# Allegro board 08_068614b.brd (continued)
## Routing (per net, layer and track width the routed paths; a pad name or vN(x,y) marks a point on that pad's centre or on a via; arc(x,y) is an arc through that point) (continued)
V5_N: length 69.3
  L2_PWR w0.5: v2(94.05,31.26) 94.05,34.06 94.04,34.07
  L2_PWR w0.508: v2(119.35,43.48) v2(119.35,41.9) 119.35,39.47 113.13,33.25 v2(105.51,33.25) 104.69,34.07 101.48,34.07 ; 101.48,34.07 94.04,34.07 88.03,40.08 88.03,43.81 v2(87.46,44.38) 87.46,45.06 ; 101.48,34.07 v2(101.48,40.79) ; v2(89.77,45.06) 87.46,45.06 ; 87.46,45.06 v2(87.46,45.74)
  BOTTOM w0.2: U2.16 v2(101.48,40.79) ; U2.6 104.81,35.2 C52.1 ; R72.1 v2(119.35,41.9) ; R70.1 v2(119.35,43.48)
  BOTTOM w0.508: C52.1 v2(105.51,33.25) ; R68.1 v2(94.05,31.26) ; R61.2 v2(87.46,44.38) ; R82.1 v2(89.77,45.06) ; R78.1 v2(87.46,45.74)
V5_P: length 204.7
  L2_PWR w0.5: v2(89.64,126.94) 90.96,125.62
  L2_PWR w0.508: 105.38,121.2 105.38,125.62 ; 105.38,121.2 v2(105.38,121.19) ; 105.38,121.2 102.43,118.25 95.85,118.25 94.74,117.14 v2(94.74,116.13) ; 105.38,125.62 105.38,125.69 105.89,126.21 118.03,126.21 119.23,127.41 v2(119.23,129.84) v2(119.23,131.42) ; 105.38,125.62 90.96,125.62
  L3_SIG w0.6: 36.04,130.63 89.64,130.63 ; 89.64,130.63 v2(89.64,129.84) v2(89.64,126.94) ; 89.64,130.63 v2(89.64,131.42) v2(89.64,133)
  L3_SIG w0.635: v2(42.75,54.31) v2(42.75,55.01) v2(42.75,55.72) 32.4,66.08 32.4,126.99 36.04,130.63
  BOTTOM w0.2: U1.6 104.68,125.22
  BOTTOM w0.3: 104.68,125.22 104.68,123.15 C8.1
  BOTTOM w0.508: C8.1 v2(105.38,121.19) ; R25.1 v2(89.64,126.94) ; R22.1 v2(89.64,133) ; R15.1 v2(119.23,129.84) ; R13.1 v2(119.23,131.42) ; R7.2 v2(89.64,129.84) ; R11.1 v2(94.74,116.13) ; R24.1 v2(89.64,131.42)
VIN: length 50.2
  TOP w0.581: DS2.A v2(42.13,60.91)
  TOP w0.635: DS1.A v2(44.09,143.69)
  L4_SIG w0.508: v2(42.13,60.91) 35.79,67.24 v1(35.79,94.19)
  BOTTOM w0.581: 43.29,60.91 R65.1 43.29,62.39 44.02,63.12 R83.1 ; 43.29,60.91 R59.1 ; 43.29,60.91 v2(42.13,60.91)
  BOTTOM w0.635: R117.1 36.73,127.89 ; R117.1 36.02,128.46 ; R117.1 35.31,127.89 ; R28.1 46.85,143.69 v2(44.09,143.69)
  vias: v1(17.28,163.47) v1(17.28,160.93) v1(17.28,158.39) v1(17.28,155.85) v1(18.18,145.73) v1(18.18,120.33) v1(18.55,162.2) v1(18.55,159.66) v1(18.55,157.12) v1(19.82,163.47) v1(19.82,160.93) v1(19.82,158.39) v1(19.82,155.85) v1(19.81,149.59) v1(19.81,141.87) v1(19.81,124.19) v1(19.81,116.47) v1(21.09,157.11) v1(22.36,158.38) v1(22.36,155.84) v1(23.63,157.11) v1(23.67,151.22) v1(23.67,140.23) v1(23.67,125.82) v1(23.67,114.83) v1(24.9,158.38) v1(24.9,155.84) v1(26.17,157.11) v1(27.44,163.46) v1(27.44,160.92) v1(27.44,158.38) v1(27.44,155.84) v1(27.53,149.59) v1(27.53,141.87) v1(27.53,124.19) v1(27.53,116.47) v1(28.71,162.19) v1(28.71,159.65) v1(28.71,157.11) v1(29.16,145.73) v1(29.16,120.33) v1(29.98,163.46) v1(29.98,160.92) v1(29.98,158.38) v1(29.98,155.84) v1(35.78,106.89) v1(35.78,104.35) v1(35.78,101.81) v1(35.78,99.27) v1(35.79,96.73) v1(37.05,105.62) v1(37.05,103.08) v1(37.05,100.54) v1(37.05,98) v1(37.06,95.46) v1(38.32,106.89) v1(38.32,104.35) v1(38.32,101.81) v1(38.32,99.27) v1(38.33,96.73) v1(38.33,94.19) v1(39.59,105.62) v1(39.6,95.46) v1(40.86,106.89) v1(40.86,104.35) v1(40.87,96.73) v1(40.87,94.19) v1(42.13,105.62) v1(42.14,95.46) v1(43.4,106.89) v1(43.4,104.35) v1(43.41,96.73) v1(43.41,94.19)
DRVCC_N: length 22.5
  L3_SIG w0.5: v2(96.62,49.47) v2(97.39,49.47) 98.73,48.13 v2(103.43,48.13) v2(104.2,48.13) 110.38,48.13 v2(111.73,49.47) v2(112.5,49.47)
  BOTTOM w0.2: 104.44,49.42 104.44,49.8 ; 104.44,49.42 C51.2 103.19,49.42 103.81,48.8 U2.29 ; 104.44,49.42 104.44,49.04
DRVCC_P: length 20.9
  L3_SIG w0.625: v2(96.49,137.41) v2(97.26,137.41) 98.24,136.44 v2(103.31,136.44) v2(104.08,136.44) 110.63,136.44 v2(111.6,137.41) v2(112.37,137.41)
  BOTTOM w0.2: v2(97.26,137.41) v2(96.49,137.41) ; v2(104.08,136.44) v2(103.31,136.44) ; 103.68,136.74 U1.29
FAULT_N: length 80.2
  L3_SIG w0.2: v2(99.4,42.29) 97.79,42.29 94.96,45.12 92.85,45.12 v2(92.78,45.06) 92.43,45.06 91.4,44.03 91.4,41.39 90.44,40.43 54.61,40.43 48.4,46.64 48.4,64.82 v2(49.14,65.56)
  BOTTOM w0.2: U2.19 v2(99.4,42.29) ; Q15.1 v2(49.14,65.56) ; R82.2 v2(92.78,45.06)
PGATE: length 4.1
  BOTTOM w0.2: 105.68,134.74 U1.33
  BOTTOM w0.3: R27.2 107.79,136.32 107.28,135.81 106.49,135.81 105.68,135 105.68,134.74
RUN_N: length 18.4
  L3_SIG w0.2: v2(92.78,41.9) 92.78,40.38 94.37,38.8 99.25,38.8 100.49,40.04 100.49,41.36 100.92,41.79 v2(101.48,41.79)
  BOTTOM w0.2: R66.2 89.71,41.15 91.28,41.15 R67.1 v2(92.78,41.9) ; U2.18 v2(101.48,41.79)
RUN_P: length 145.3
  L3_SIG w0.2: v2(101.35,129.73) 101.92,129.16 101.92,127.98 99.93,125.99 P5.2 35.46,125.99 34.25,124.78 34.25,66.67 v2(45.01,55.91)
  BOTTOM w0.2: U1.18 v2(101.35,129.73)
UNNAMED_7_CAP_I29_N2: length 7.5
  BOTTOM w0.2: C5.2 98.17,122.46 99.72,122.46 102.18,124.93 U1.11
UNNAMED_7_CAP_I48_N1: length 1
  BOTTOM w0.2: R8.2 111.71,117.85 C4.1
UNNAMED_7_CAP_I49_N1: length 9
  BOTTOM w0.2: U1.3 106.18,125.13 109.14,122.17 111.04,122.17 111.29,121.92 111.29,121.57 C3.1 111.71,121.15 R8.1
UNNAMED_7_CAP_I67_N1: length 1
  BOTTOM w0.2: R5.2 109.31,117.85 C2.1
UNNAMED_7_CAP_I68_N1: length 7.1
  BOTTOM w0.2: U1.4 105.68,125.06 108.92,121.82 108.92,121.55 C1.1 109.31,121.15 R5.1
UNNAMED_7_CAP_I69_N2: length 1.6
  BOTTOM w0.2: U1.1 107.18,125.5 107.38,125.3 108.02,125.3 C6.2
UNNAMED_7_CAP_I83_N2: length 6.9
  BOTTOM w0.2: 104.68,134.74 U1.31
  BOTTOM w0.3: 104.68,134.74 104.68,135.01 105.83,136.16 C9.2 106.63,137.63 106.63,139.13 105.86,139.9 R31.1
UNNAMED_7_CAP_I87_N1: length 50.9
  TOP w0.2: Q5.2 v1(82.87,157.18) ; Q9.3 v1(90.09,157.18) ; Q5.3 v1(84.15,157.18) ; Q5.1 v1(81.59,157.18) ; Q9.1 v1(87.53,157.18) ; Q9.2 v1(88.81,157.18)
  L4_SIG w1: v2(95.11,123.96) 97.85,126.71 97.85,130.41 97.85,130.41 v2(97.85,131.36) 97.85,132.75 97.85,132.76 97.85,133.78 84.27,147.36 TP3.1
  BOTTOM w0.2: R45.1 94.42,125.44 95.11,124.75 v2(95.11,123.96) R43.1 ; 99.56,132.23 U1.23
  BOTTOM w0.3: 99.56,132.23 98.75,131.42 C11.1
  BOTTOM w0.5: C11.1 v2(97.85,131.36)
  vias: v1(79.44,149.97) v1(79.44,148.63) v1(79.44,147.3) v1(79.44,145.97) v1(80.77,149.97) v1(80.77,148.63) v1(80.77,147.3) v1(80.77,145.97) v1(90,155.91) v1(90,154.58) v1(90,153.25) v1(90,151.91) v1(90,149.97) v1(90,148.63) v1(90,147.3) v1(90,145.97) v1(91.33,155.91) v1(91.33,154.58) v1(91.33,153.25) v1(91.33,151.91) v1(91.33,149.97) v1(91.33,148.63) v1(91.33,147.3) v1(91.33,145.97) v1(92.67,155.91) v1(92.67,154.58) v1(92.67,153.25) v1(92.67,151.91) v1(92.67,149.97) v1(92.67,148.63) v1(92.67,147.3) v1(92.67,145.97)
UNNAMED_7_CAP_I93_N1: length 52.3
  TOP w0.2: Q7.2 v1(118.95,157.18) ; Q7.1 v1(117.67,157.18) ; Q7.3 v1(120.23,157.18) ; Q11.1 v1(123.61,157.18) ; Q11.2 v1(124.9,157.18) ; Q11.3 v1(126.18,157.18)
  L4_SIG w1: TP6.1 124.77,147.86 111.02,134.11 v2(111.02,131.36) 111.02,126.71 v2(113.76,123.96)
  BOTTOM w0.2: R46.1 v2(113.76,123.96) 113.76,124.76 114.44,125.44 R50.1 ; 120.38,148.64 120.38,147.3 ; 109.31,132.23 U1.38
  BOTTOM w0.3: C10.1 110.12,131.42 109.31,132.23
  BOTTOM w0.5: C10.1 v2(111.02,131.36)
  vias: v1(116.38,155.92) v1(116.38,154.58) v1(116.38,153.25) v1(116.38,151.92) v1(116.38,149.97) v1(116.38,148.64) v1(116.38,147.3) v1(116.38,145.97) v1(117.71,155.92) v1(117.71,154.58) v1(117.71,153.25) v1(117.71,151.92) v1(117.71,149.97) v1(117.71,148.64) v1(117.71,147.3) v1(117.71,145.97) v1(119.04,155.92) v1(119.04,154.58) v1(119.04,153.25) v1(119.04,151.92) v1(119.04,149.97) v1(119.04,148.64) v1(119.04,147.3) v1(119.04,145.97) v1(128.27,149.97) v1(128.27,148.63) v1(128.27,147.3) v1(128.27,145.97) v1(129.6,149.97) v1(129.6,148.63) v1(129.6,147.3) v1(129.6,145.97)
UNNAMED_7_CAP_I127_N1: length 7.3
  BOTTOM w0.2: 102.68,134.74 U1.27
  BOTTOM w0.3: R36.1 101.35,140.24 100.71,139.61 100.71,137.63 C12.1 101.51,136.19 102.68,135.02 102.68,134.74
UNNAMED_7_CAP_I149_N1: length 29.2
  TOP w0.2: R2.1 v2(127.71,123.18)
  L4_SIG w0.2: v2(127.71,123.18) 127.12,123.77 120.2,123.77 115.22,128.75 114.06,128.75 113.84,128.52 v2(113.84,127.73)
  BOTTOM w0.2: v2(113.84,127.73) 113.84,127.27 113.51,126.94 C26.1 113,125.41 R49.1 ; v2(113.84,127.73) 113.84,128.16 113.48,128.52 C29.1 ; v2(113.84,127.73) U1.47 ; R56.1 v2(127.71,123.18)
UNNAMED_7_CAP_I149_N2: length 6.2
  BOTTOM w0.2: U1.48 111.31,127.23 C26.2 111.6,125.41 R49.2 111.55,124.02 R46.2
UNNAMED_7_CAP_I199_N1: length 29
  TOP w0.2: R1.3 v2(81.33,123.18)
  L4_SIG w0.2: v2(81.33,123.18) 81.92,123.77 88.55,123.77 93.47,128.69 94.83,128.69 95.03,128.49 v2(95.03,127.73)
  BOTTOM w0.2: U1.14 v2(95.03,127.73) ; v2(95.03,127.73) 95.03,127.27 95.35,126.94 C25.1 95.86,125.41 R44.1 ; v2(95.03,127.73) 95.03,128.16 95.39,128.52 C27.1 ; R54.1 v2(81.33,123.18)
UNNAMED_7_CAP_I199_N2: length 8.9
  BOTTOM w0.2: 97.26,129.29 C27.2 97.55,128.23 U1.15 ; 97.26,129.29 94.65,129.29 93.8,128.44 R45.2 ; 97.26,129.29 97.26,130.05 R47.1
UNNAMED_7_CAP_I202_N2: length 6.2
  BOTTOM w0.2: U1.13 97.55,127.23 C25.2 97.26,125.41 R44.2 97.31,124.02 R43.2
UNNAMED_7_DIOLED_I185_N: length 2.3
  TOP w0.635: DS1.C v2(46.34,141.09)
  BOTTOM w0.635: R30.1 46.69,141.44 v2(46.34,141.09)
UNNAMED_7_ICLTC3871_I31_BOOST1: length 1.2
  BOTTOM w0.2: 108.55,133.6 U1.37
  BOTTOM w0.3: R119.1 108.55,133.6
UNNAMED_7_ICLTC3871_I31_BOOST2: length 1.2
  BOTTOM w0.2: 100.31,133.6 U1.24
  BOTTOM w0.3: R57.1 100.31,133.6
UNNAMED_7_ICLTC3871_I31_BUCK: length 14.9
  L3_SIG w0.2: v2(92.66,126.94) 99.56,126.94 v2(101.35,128.73)
  BOTTOM w0.2: v2(92.66,126.94) R25.2 91.15,126.2 89.6,126.2 88.87,126.93 R116.1 ; U1.16 v2(101.35,128.73)
UNNAMED_7_ICLTC3871_I31_DRVSET: length 15.1
  L3_SIG w0.2: v2(92.66,133) 94.87,130.78 101.3,130.78 v2(101.35,130.73)
  BOTTOM w0.2: U1.20 v2(101.35,130.73) ; R23.1 88.87,132.99 89.6,132.26 91.15,132.26 R22.2 v2(92.66,133)
UNNAMED_7_ICLTC3871_I31_FAULTN: length 63
  L3_SIG w0.2: v2(50.3,149.94) 50.3,145.72 61.67,134.35 89.73,134.35 v2(92.66,131.42) 94.55,129.53 98,129.53 98.71,130.23 v2(99.28,130.23)
  BOTTOM w0.2: U1.19 v2(99.28,130.23) ; R24.2 v2(92.66,131.42)
  BOTTOM w0.508: Q1.1 v2(50.3,149.94)
UNNAMED_7_ICLTC3871_I31_FREQ: length 12.1
  L3_SIG w0.2: v2(107.51,129.73) 108.57,130.78 114.35,130.78 116.21,132.64 v2(116.21,133)
  BOTTOM w0.2: U1.43 v2(107.51,129.73) ; R19.2 v2(116.21,133)
UNNAMED_7_ICLTC3871_I31_ILIM: length 12.8
  L3_SIG w0.2: v2(92.66,129.84) 93.83,128.66 98.71,128.66 v2(99.28,129.23)
  BOTTOM w0.2: U1.17 v2(99.28,129.23) ; R9.2 88.87,129.83 89.6,129.09 91.15,129.09 R7.1 v2(92.66,129.84)
UNNAMED_7_ICLTC3871_I31_MODE: length 12.9
  L3_SIG w0.2: v2(116.21,129.84) 114.95,128.59 110.23,128.59 v2(109.59,129.23)
  BOTTOM w0.2: U1.44 v2(109.59,129.23) ; R16.1 119.3,129.09 117.71,129.09 R15.2 v2(116.21,129.84)
UNNAMED_7_ICLTC3871_I31_OVHIGH: length 8.6
  BOTTOM w0.2: U1.8 103.68,124.7 101.85,122.87 R21.1 101.06,120.66 R20.1
UNNAMED_7_ICLTC3871_I31_OVLOW: length 9.8
  BOTTOM w0.2: R6.2 97.9,120.66 R10.1 99.3,122.06 99.88,122.06 102.68,124.86 U1.10
UNNAMED_7_ICLTC3871_I31_PHSMD: length 15.9
  L3_SIG w0.2: v2(116.21,131.42) 114.19,129.4 110.93,129.4 110.16,130.18 109.27,130.18 107.83,128.73 v2(107.51,128.73)
  BOTTOM w0.2: v2(116.21,131.42) R13.2 117.71,130.68 119.3,130.68 R14.2 ; U1.45 v2(107.51,128.73)
UNNAMED_7_ICLTC3871_I31_SETCUR: length 11.9
  BOTTOM w0.2: U1.12 101.68,125 99.55,122.86 96.94,122.86 R12.2 94.74,120.66 R11.2
UNNAMED_7_ICLTC3871_I31_SNSD1: length 8.9
  BOTTOM w0.2: 111.6,129.29 C29.2 111.31,128.23 U1.46 ; 111.6,129.29 114.22,129.29 115.06,128.44 R50.2 ; 111.6,129.29 R52.1
UNNAMED_7_ICLTC3871_I31_TG1: length 9.6
  L2_PWR w0.508: v2(114.45,132.16) 112.62,132.16 111.95,132.83 108.61,132.83 v2(107.51,131.73)
  BOTTOM w0.2: U1.39 v2(107.51,131.73)
  BOTTOM w0.5: v2(114.45,132.16) R32.1
UNNAMED_7_ICLTC3871_I31_TG2: length 9.7
  L2_PWR w0.508: v2(94.43,132.16) 96.27,132.16 97.09,132.98 100.1,132.98 v2(101.35,131.73)
  BOTTOM w0.2: U1.22 v2(101.35,131.73)
  BOTTOM w0.5: v2(94.43,132.16) R34.1
UNNAMED_7_ICLTC3871_I31_UVHIGH: length 9
  BOTTOM w0.2: R17.1 99.48,120.66 R18.1 100.27,121.89 103.18,124.8 U1.9
UNNAMED_7_IND_I144_N2: length 1.9
  BOTTOM w0.2: R53.2 v2(131.84,124.76)
  vias: v1(128.27,139.82) v1(128.27,138.48) v1(128.27,137.15) v1(128.27,135.82) v1(129.6,139.82) v1(129.6,138.48) v1(129.6,137.15) v1(129.6,135.82) v1(130.51,128.9) v1(131.84,128.9) v1(133.18,128.9)
UNNAMED_7_IND_I265_N1: length 1.9
  BOTTOM w0.2: R48.2 v2(77.21,124.76)
  vias: v1(75.88,128.9) v1(77.21,128.9) v1(78.55,128.9) v1(79.44,139.82) v1(79.44,138.48) v1(79.44,137.15) v1(79.44,135.82) v1(80.77,139.82) v1(80.77,138.48) v1(80.77,137.15) v1(80.77,135.82)
UNNAMED_7_NCTESTPAD_I102_N1: length 23.9
  TOP w0.65: Q12.4 v1(114.32,145.01) ; Q8.4 v1(114.32,150.95)
  L4_SIG w1: v2(111,138.58) 111,138.61 114.32,141.94 v1(114.32,145.01) v1(114.32,150.95) 114.36,150.99 TP8.1
  BOTTOM w0.508: R33.2 v2(111,138.58)
UNNAMED_7_NCTESTPAD_I215_N1: length 45.7
  TOP w0.65: Q5.4 v1(86.47,158.48) ; Q9.4 v1(92.41,158.48)
  L3_SIG w1: TP4.1 79.57,158.48 v1(86.47,158.48) v1(92.41,158.48)
  L4_SIG w1: v2(93.32,134.61) 82.32,145.61 82.32,153.03 79.53,155.82 TP4.1
  BOTTOM w0.5: R34.2 94.31,134.61 v2(93.32,134.61)
UNNAMED_7_NCTESTPAD_I219_N1: length 24.8
  TOP w0.65: Q6.4 v1(94.72,150.93) ; Q10.4 94.72,157.85 TP5.1
  L4_SIG w1: v2(97.86,138.58) 97.86,138.59 94.72,141.74 v1(94.72,150.93) 94.68,150.96 TP5.1
  BOTTOM w0.508: R35.2 v2(97.86,138.58)
UNNAMED_7_RES_I45_N2: length 40.9
  TOP w0.65: TP7.1 129.46,158.48 Q11.4 ; Q7.4 v1(122.55,158.48)
  L3_SIG w1: v1(122.55,158.48) 129.46,158.48 TP7.1
  L4_SIG w1: TP7.1 129.51,156.84 126.67,154 126.67,145.73 v2(115.55,134.61)
  BOTTOM w0.5: R32.2 114.57,134.61 v2(115.55,134.61)
UNNAMED_7_RES_I133_N1: length 1.1
  BOTTOM w0.2: R37.2 107.01,117.95 R38.1
UNNAMED_7_RES_I157_N1: length 0.8
  BOTTOM w0.2: R41.1 R40.1
UNNAMED_7_RES_I157_N2: length 10.8
  BOTTOM w0.2: R42.1 113.91,120.45 R41.2 113.69,121.47 113.69,121.82 112.95,122.57 109.3,122.57 106.68,125.19 U1.2
UNNAMED_7_RES_I183_N2: length 2.4
  BOTTOM w0.635: R30.2 49.31,141.74 Q4.3
UNNAMED_7_RES_I188_N1: length 68
  L4_SIG w0.635: v2(107.4,139.46) 107.4,163.11 112.15,167.86 v1(138.44,167.86) v1(138.44,175.22)
  BOTTOM w0.2: v2(107.4,139.46) 107.4,138.78 107.6,138.58 R27.1
  BOTTOM w0.508: Q2.1 v1(138.44,167.86) ; Q3.1 v1(138.44,175.22)
UNNAMED_7_RES_I194_N1: length 20.1
  TOP w0.2: R2.3 v2(127.71,124.76)
  L4_SIG w0.2: v2(113.86,130.05) 113.86,129.35 114.06,129.15 115.43,129.15 120.41,124.17 127.11,124.17 v2(127.71,124.76)
  BOTTOM w0.2: R53.1 v2(127.71,124.76) ; R52.2 v2(113.86,130.05)
UNNAMED_7_RES_I205_N2: length 20.1
  TOP w0.2: R1.1 v2(81.33,124.76)
  L4_SIG w0.2: v2(81.33,124.76) 81.93,124.17 88.38,124.17 93.3,129.09 94.83,129.09 95.05,129.31 v2(95.05,130.1)
  BOTTOM w0.2: R47.2 v2(95.05,130.1) ; R48.1 v2(81.33,124.76)
UNNAMED_7_TRAN2N7002_I177_D: length 4.7
  BOTTOM w0.635: R28.2 49.31,144.04 Q4.1 50.49,144.25 R29.1 50.49,146.22 Q1.3
UNNAMED_9_CAP_I9_N1: length 7.1
  BOTTOM w0.2: U2.4 105.81,37.12 109.05,33.88 109.05,33.61 C45.1 109.44,33.21 R58.1
UNNAMED_9_CAP_I11_N1: length 1
  BOTTOM w0.2: R58.2 109.44,29.91 C46.1
UNNAMED_9_CAP_I13_N1: length 9
  BOTTOM w0.2: U2.3 106.31,37.18 109.29,34.2 111.2,34.2 111.42,33.97 111.42,33.63 C47.1 111.84,33.21 R62.1
UNNAMED_9_CAP_I15_N1: length 1
  BOTTOM w0.2: R62.2 111.84,29.91 C48.1
UNNAMED_9_CAP_I43_N2: length 7.5
  BOTTOM w0.2: U2.11 102.31,36.99 99.84,34.52 98.3,34.52 C49.2
UNNAMED_9_CAP_I53_N2: length 1.6
  BOTTOM w0.2: U2.1 107.31,37.56 107.51,37.36 108.15,37.36 C50.2
UNNAMED_9_CAP_I61_N2: length 7.3
  BOTTOM w0.2: 104.81,46.8 U2.31
  BOTTOM w0.3: 104.81,46.8 104.81,47.18 105.86,48.23 105.86,48.58 C53.2 106.42,48.89 106.96,49.43 106.96,51.47 106.47,51.95 R86.1
UNNAMED_9_CAP_I91_N1: length 59.4
  TOP w0.2: Q21.3 v1(84.65,76.93) ; Q17.3 v1(90.6,76.93) ; Q17.2 v1(89.32,76.93) ; Q21.2 v1(83.37,76.93) ; Q21.1 v1(82.09,76.93) ; Q17.1 v1(88.04,76.93)
  L4_SIG w1: v2(95.23,36.02) 95.23,36.92 97.98,39.66 v2(97.98,43.42) 97.98,43.86 99.1,44.98 99.1,49.69 96.58,52.21 96.58,57.34 84.78,69.14 TP11.1
  BOTTOM w0.2: R98.1 v2(95.23,36.02) 95.23,36.81 94.55,37.5 R100.1 ; 99.68,44.29 U2.23
  BOTTOM w0.3: 99.68,44.29 98.88,43.48 C55.1
  BOTTOM w0.5: C55.1 v2(97.98,43.42)
  vias: v1(79.95,69.72) v1(79.95,68.39) v1(79.95,67.05) v1(79.95,65.72) v1(81.28,69.72) v1(81.28,68.39) v1(81.28,67.05) v1(81.28,65.72) v1(90.51,75.67) v1(90.51,74.33) v1(90.51,73) v1(90.51,71.66) v1(90.51,69.72) v1(90.51,68.38) v1(90.51,67.05) v1(90.51,65.72) v1(91.84,75.67) v1(91.84,74.33) v1(91.84,73) v1(91.84,71.66) v1(91.84,69.72) v1(91.84,68.38) v1(91.84,67.05) v1(91.84,65.72) v1(93.17,75.67) v1(93.17,74.33) v1(93.17,73) v1(93.17,71.66) v1(93.17,69.72) v1(93.17,68.38) v1(93.17,67.05) v1(93.17,65.72)
UNNAMED_9_CAP_I93_N1: length 59.4
  TOP w0.2: Q23.3 v1(125.82,76.93) ; Q19.2 v1(118.59,76.93) ; Q19.3 v1(119.87,76.93) ; Q23.1 v1(123.26,76.93) ; Q19.1 v1(117.31,76.93) ; Q23.2 v1(124.54,76.93)
  L4_SIG w1: v2(113.89,36.02) 113.89,36.92 111.14,39.66 v2(111.14,43.42) 111.14,43.84 110.02,44.96 110.02,49.67 112.54,52.19 112.54,57.29 124.41,69.17 TP14.1
  BOTTOM w0.2: R101.1 v2(113.89,36.02) 113.89,36.82 114.56,37.5 R105.1 ; 109.43,44.29 U2.38
  BOTTOM w0.3: C54.1 110.24,43.48 109.43,44.29
  BOTTOM w0.5: C54.1 v2(111.14,43.42)
  vias: v1(116.02,75.67) v1(116.02,74.34) v1(116.02,73) v1(116.02,71.67) v1(116.02,69.72) v1(116.02,68.39) v1(116.02,67.05) v1(116.02,65.72) v1(117.35,75.67) v1(117.35,74.34) v1(117.35,73) v1(117.35,71.67) v1(117.35,69.72) v1(117.35,68.39) v1(117.35,67.05) v1(117.35,65.72) v1(118.69,75.67) v1(118.69,74.34) v1(118.69,73) v1(118.69,71.67) v1(118.69,69.72) v1(118.69,68.39) v1(118.69,67.05) v1(118.69,65.72) v1(127.92,69.72) v1(127.92,68.39) v1(127.92,67.05) v1(127.92,65.72) v1(129.25,69.72) v1(129.25,68.39) v1(129.25,67.05) v1(129.25,65.72)
UNNAMED_9_CAP_I95_N1: length 7.7
  BOTTOM w0.2: 102.81,46.8 U2.27
  BOTTOM w0.3: R91.1 101.17,52.3 100.75,51.88 100.75,49.55 101.41,48.89 C56.1 101.94,48.61 101.94,48.05 102.81,47.18 102.81,46.8
UNNAMED_9_CAP_I126_N1: length 28.7
  TOP w0.2: R3.1 v2(94.51,53.37)
  L5_GND w0.2: v2(95.15,39.79) 95.15,40.55 95.38,40.77 96.38,40.77 97.12,41.52 97.12,47.59 93.93,50.78 93.93,52.78 v2(94.51,53.37)
  BOTTOM w0.2: C74.1 95.51,40.58 95.15,40.22 v2(95.15,39.79) ; v2(95.15,39.79) U2.14 ; v2(95.15,39.79) 95.15,39.32 95.48,39 C69.1 95.99,37.47 R99.1 ; R109.1 94.51,53.37 v2(94.51,53.37)
UNNAMED_9_CAP_I126_N2: length 6.2
  BOTTOM w0.2: R98.2 97.44,36.08 R99.2 97.39,37.47 C69.2 97.68,39.29 U2.13
UNNAMED_9_CAP_I130_N2: length 8.9
  BOTTOM w0.2: U2.15 97.68,40.29 C74.2 97.39,41.34 ; 97.39,41.34 94.78,41.34 93.93,40.5 R100.2 ; 97.39,41.34 97.39,42.11 R102.1
UNNAMED_9_CAP_I138_N1: length 28.7
  TOP w0.2: R4.3 v2(114.66,53.37)
  L5_GND w0.2: v2(114.66,53.37) 115.24,52.78 115.24,50.76 112.02,47.54 112.02,41.54 112.79,40.77 113.77,40.77 113.97,40.57 v2(113.97,39.79)
  BOTTOM w0.2: R111.1 114.66,53.37 v2(114.66,53.37) ; U2.47 v2(113.97,39.79) ; v2(113.97,39.79) 113.97,40.22 113.6,40.58 C77.1 ; v2(113.97,39.79) 113.97,39.32 113.64,39 C71.1 113.13,37.47 R104.1
UNNAMED_9_CAP_I138_N2: length 6.2
  BOTTOM w0.2: U2.48 111.44,39.29 C71.2 111.73,37.47 R104.2 111.68,36.08 R101.2
UNNAMED_9_CAP_I143_N2: length 8.9
  BOTTOM w0.2: 111.73,41.34 C77.2 111.44,40.29 U2.46 ; 111.73,41.34 R107.1 ; 111.73,41.34 114.34,41.34 115.19,40.5 R105.2
UNNAMED_9_DIOLED_I242_N: length 10.9
  TOP w0.581: DS2.C v2(42.13,64.38)
  L4_SIG w0.635: v2(46.49,71.68) 46.49,68.75 v2(42.13,64.38)
  BOTTOM w0.2: v2(46.49,71.68) 46.49,71.3 46.49,71.3 R85.1
UNNAMED_9_ICLTC3871_I21_BOOST1: length 1.2
  BOTTOM w0.2: 108.68,45.65 U2.37
  BOTTOM w0.3: R123.1 108.68,45.65
UNNAMED_9_ICLTC3871_I21_BOOST2: length 1.2
  BOTTOM w0.2: 100.44,45.65 U2.24
  BOTTOM w0.3: R122.1 100.44,45.65
UNNAMED_9_ICLTC3871_I21_DRVSET: length 16.3
  L3_SIG w0.2: v2(92.78,46.64) 94.85,46.64 95.49,47.28 96.99,47.28 v2(101.48,42.79)
  BOTTOM w0.2: v2(92.78,46.64) R79.1 91.28,45.9 89.71,45.9 R78.2 ; U2.20 v2(101.48,42.79)
UNNAMED_9_ICLTC3871_I21_FREQ: length 12.4
  L3_SIG w0.2: v2(116.34,45.06) 116.34,44.76 114.43,42.85 108.13,42.85 107.64,42.36 v2(107.64,41.79)
  BOTTOM w0.2: U2.43 v2(107.64,41.79) ; R77.1 v2(116.34,45.06)
UNNAMED_9_ICLTC3871_I21_ILIM: length 13.5
  L3_SIG w0.2: v2(92.78,43.48) 93.35,43.48 93.94,42.89 93.94,42.02 94.68,41.29 v2(99.4,41.29)
  BOTTOM w0.2: v2(92.78,43.48) R63.2 91.28,42.73 89.71,42.73 R61.1 ; U2.17 v2(99.4,41.29)
UNNAMED_9_ICLTC3871_I21_MODE: length 13.1
  L3_SIG w0.2: v2(109.72,41.29) 110.59,40.41 114.85,40.41 v2(116.34,41.9)
  BOTTOM w0.2: U2.44 v2(109.72,41.29) ; v2(116.34,41.9) R72.2 117.84,41.15 119.43,41.15 R74.1
UNNAMED_9_ICLTC3871_I21_OVHIGH: length 8.6
  BOTTOM w0.2: U2.8 103.81,36.75 101.98,34.92 R81.1 101.19,32.72 R80.1
UNNAMED_9_ICLTC3871_I21_OVLOW: length 9.8
  BOTTOM w0.2: U2.10 102.81,36.92 100.01,34.12 99.43,34.12 R69.1 98.03,32.72 R64.2
UNNAMED_9_ICLTC3871_I21_PHSMD: length 16.3
  L3_SIG w0.2: v2(116.34,43.48) 116.34,43.16 114.43,41.25 111.12,41.25 110.13,42.24 109.45,42.24 107.99,40.79 v2(107.64,40.79)
  BOTTOM w0.2: U2.45 v2(107.64,40.79) ; v2(116.34,43.48) R70.2 117.84,42.73 119.43,42.73 R71.2
UNNAMED_9_ICLTC3871_I21_SETCUR: length 10.1
  BOTTOM w0.2: U2.12 101.81,37.05 99.68,34.92 97.06,34.92 95.65,33.51 R73.1 94.06,33.51 R68.2
UNNAMED_9_ICLTC3871_I21_TG1: length 9.6
  L2_PWR w0.508: v2(114.58,44.21) 112.64,44.21 111.9,44.95 108.8,44.95 v2(107.64,43.79)
  BOTTOM w0.2: U2.39 v2(107.64,43.79)
  BOTTOM w0.508: R87.1 v2(114.58,44.21)
UNNAMED_9_ICLTC3871_I21_TG2: length 9.7
  L2_PWR w0.508: v2(94.54,44.21) 96.31,44.21 97.12,45.03 100.24,45.03 v2(101.48,43.79)
  BOTTOM w0.2: U2.22 v2(101.48,43.79)
  BOTTOM w0.508: R89.1 v2(94.54,44.21)
UNNAMED_9_ICLTC3871_I21_UVHIGH: length 9
  BOTTOM w0.2: R75.1 99.61,32.72 R76.1 100.4,33.94 103.31,36.86 U2.9
UNNAMED_9_ICLTC3871_I21_VFBLOW: length 10.8
  BOTTOM w0.2: U2.2 106.81,37.25 109.46,34.6 113.1,34.6 113.82,33.88 113.82,33.53 R96.2 114.04,32.51 R97.1
UNNAMED_9_IND_I114_N1: length 1.9
  BOTTOM w0.2: v2(92.93,57.5) 92.93,55.62 R103.2
  vias: v1(79.95,59.57) v1(79.95,58.24) v1(79.95,56.9) v1(79.95,55.57) v1(81.28,59.57) v1(81.28,58.24) v1(81.28,56.9) v1(81.28,55.57) v1(89.2,58.84) v1(89.2,57.51) v1(89.2,56.17)
UNNAMED_9_IND_I133_N2: length 1.9
  BOTTOM w0.2: v2(116.24,57.5) 116.23,57.49 R108.2
  vias: v1(119.96,58.81) v1(119.96,57.48) v1(119.96,56.15) v1(127.92,59.57) v1(127.92,58.24) v1(127.92,56.9) v1(127.92,55.57) v1(129.25,59.57) v1(129.25,58.24) v1(129.25,56.9) v1(129.25,55.57)
UNNAMED_9_NCTESTPAD_I80_N1: length 31.7
  TOP w0.508: Q22.4 v1(95.23,70.68)
  TOP w0.66: TP13.1 95.23,77.6 Q18.4
  L4_SIG w1: TP13.1 95.23,77.6 v1(95.23,70.68) 95.23,64.8 99.1,60.93 v2(99.1,52.49)
  BOTTOM w0.5: R90.2 99.09,52.48 v2(99.1,52.49)
UNNAMED_9_NCTESTPAD_I83_N1: length 52.5
  TOP w0.508: Q17.4 v1(92.92,78.24) ; Q21.4 v1(86.97,78.24)
  L3_SIG w1: TP12.1 80.08,78.24 v1(86.97,78.24) v1(92.92,78.24)
  L4_SIG w1: v2(94.54,47.81) 82.92,59.43 82.92,73.7 80.04,76.57 TP12.1
  BOTTOM w0.508: R89.2 v2(94.54,47.81)
UNNAMED_9_NCTESTPAD_I104_N1: length 30.7
  TOP w0.508: Q24.4 v1(113.97,70.71) ; Q20.4 v1(113.97,64.76)
  L4_SIG w1: TP16.1 113.97,77.6 v1(113.97,70.71) v1(113.97,64.76) 110.02,60.81 v2(110.02,52.51)
  BOTTOM w0.5: v2(110.02,52.51) 110.03,52.5 R88.2
UNNAMED_9_NCTESTPAD_I109_N1: length 47.6
  TOP w0.508: Q19.4 v1(122.19,78.24)
  TOP w0.65: Q23.4 129.11,78.24 TP15.1
  L3_SIG w1: v1(122.19,78.24) 129.11,78.24 TP15.1
  L4_SIG w1: TP15.1 129.15,76.52 126.3,73.67 126.3,59.54 v2(114.58,47.81)
  BOTTOM w0.508: R87.2 v2(114.58,47.81)
UNNAMED_9_RES_I102_N1: length 0.8
  BOTTOM w0.2: R96.1 R95.1
UNNAMED_9_RES_I115_N1: length 19
  TOP w0.2: R3.3 v2(92.93,53.37)
  L5_GND w0.2: v2(92.93,53.37) 93.53,52.77 93.53,50.62 96.72,47.42 96.72,41.69 96.21,41.18 95.38,41.18 95.18,41.38 v2(95.18,42.16)
  BOTTOM w0.2: R102.2 v2(95.18,42.16) ; R103.1 92.94,53.37 v2(92.93,53.37)
UNNAMED_9_RES_I134_N1: length 19
  TOP w0.2: R4.1 v2(116.24,53.37)
  L5_GND w0.2: v2(116.24,53.37) 115.64,52.77 115.64,50.59 112.42,47.37 112.42,41.71 112.95,41.18 113.79,41.18 113.99,41.38 v2(113.99,42.11)
  BOTTOM w0.2: R108.1 116.24,54.11 v2(116.24,53.37) ; R107.2 v2(113.99,42.11)
UNNAMED_9_RES_I145_N1: length 1.1
  BOTTOM w0.2: R92.2 107.14,30.01 R93.1
UNNAMED_9_RES_I232_N1: length 2.9
  BOTTOM w0.2: R59.2 46.09,59.93 Q14.1 46.09,58.73 R60.1
UNNAMED_9_RES_I232_N2: length 2.9
  BOTTOM w0.2: Q13.3 48.19,55.95 47.31,56.83 R60.2
UNNAMED_9_RES_I235_N1: length 54
  L3_SIG w0.2: v2(49.37,60.89) 49.37,48.9 56.37,41.9 v2(86.7,41.9)
  BOTTOM w0.2: R66.1 v2(86.7,41.9) ; Q14.3 v2(49.37,60.89)
UNNAMED_9_RES_I236_N2: length 1.3
  BOTTOM w0.2: R65.2 Q14.2
UNNAMED_9_RES_I239_N1: length 6.1
  BOTTOM w0.2: Q15.3 44.81,64.62 R83.2 44.59,64.84 R84.1 45.88,67.6 Q16.1
UNNAMED_9_RES_I244_N2: length 2.7
  BOTTOM w0.2: Q16.3 48.19,68.35 47.99,68.55 R85.2
UNNAMED_9_RES_I291_N2: length 2.4
  BOTTOM w0.2: Q13.1 45.07,55.01 R120.2 44.97,54.08 R121.1
VFBHIGH_N: length 6.4
  BOTTOM w0.2: U2.5 105.31,36.98 106.94,35.35 R94.1 107.14,33.11 R93.2
VFBHIGH_P: length 6.4
  BOTTOM w0.2: R38.2 107.01,121.05 R39.1 106.81,123.29 105.18,124.92 U1.5
VHIGH: length 99.6
  TOP w0.6: J1.1 161.55,165.15 161.14,165.56 C115.2
  L4_SIG w0.508: v2(99.48,116.13) v2(101.06,116.13) 114.3,116.13 115.44,117.27 115.44,119.94 117.31,121.81 134.23,121.81 158.15,145.73 158.15,159.5 159.87,161.22 v1(159.87,166.78)
  BOTTOM w0.2: R17.2 v2(99.48,116.13) ; R20.2 v2(101.06,116.13)
  vias: v1(17.28,173.63) v1(17.28,171.09) v1(17.28,168.55) v1(17.28,166.01) v1(18.55,172.36) v1(18.55,169.82) v1(18.55,167.28) v1(19.82,173.63) v1(19.82,171.09) v1(19.82,168.55) v1(19.82,166.01) v1(21.09,172.37) v1(22.36,173.64) v1(22.36,171.1) v1(23.63,172.37) v1(24.9,173.64) v1(24.9,171.1) v1(26.17,172.37) v1(27.44,173.64) v1(27.44,171.1) v1(27.44,168.56) v1(27.44,166.02) v1(28.71,172.37) v1(28.71,169.83) v1(28.71,167.29) v1(29.98,173.64) v1(29.98,171.1) v1(29.98,168.56) v1(29.98,166.02) v1(98.16,191.19) v1(98.16,188.65) v1(98.16,186.11) v1(99.43,189.92) v1(99.43,187.38) v1(100.7,191.19) v1(100.7,188.65) v1(100.7,186.11) v1(101.97,189.93) v1(103.24,191.2) v1(103.24,188.66) v1(104.51,189.93) v1(105.78,191.2) v1(105.78,188.66) v1(107.05,189.93) v1(108.32,191.2) v1(108.32,188.66) v1(108.32,186.12) v1(109.59,189.93) v1(109.59,187.39) v1(110.86,191.2) v1(110.86,188.66) v1(110.86,186.12) v1(142.88,178.11) v1(142.88,176.77) v1(142.88,175.44) v1(142.88,174.11) v1(142.88,170.74) v1(142.88,169.41) v1(142.88,168.07) v1(142.88,166.74) v1(144.22,178.11) v1(144.22,176.77) v1(144.22,175.44) v1(144.22,174.11) v1(144.22,170.74) v1(144.22,169.41) v1(144.22,168.07) v1(144.22,166.74) v1(145.55,178.11) v1(145.55,176.77) v1(145.55,175.44) v1(145.55,174.11) v1(145.55,170.74) v1(145.55,169.41) v1(145.55,168.07) v1(145.55,166.74) v1(146.88,178.11) v1(146.88,176.77) v1(146.88,175.44) v1(146.88,174.11) v1(146.88,170.74) v1(146.88,169.41) v1(146.88,168.07) v1(146.88,166.74) v1(155.02,188.79) v1(155.02,186.25) v1(155.02,183.71) v1(155.02,181.17) v1(155.03,178.63) v1(155.03,176.09) v1(156.29,187.52) v1(156.29,184.98) v1(156.29,182.44) v1(156.29,179.9) v1(156.3,177.36) v1(157.56,188.79) v1(157.56,186.25) v1(157.56,183.71) v1(157.56,181.17) v1(157.57,178.63) v1(157.57,176.09) v1(158.83,187.52) v1(158.84,177.36) v1(160.1,188.79) v1(160.1,186.25) v1(160.11,178.63) v1(160.11,176.09) v1(161.37,187.52) v1(161.38,177.36) v1(162.64,188.79) v1(162.64,186.25) v1(162.65,178.63) v1(162.65,176.09)
VHIGH_P: length 129.6
  L4_SIG w0.5: v2(108.31,118.65) 107.06,117.4 75.18,117.4 74.14,118.44 74.14,171.39 v1(75.23,172.47)
  L4_SIG w0.6: v1(100.78,172.53) 101.55,171.75 107.65,171.75 v1(108.37,172.47)
  L4_SIG w0.625: 104.62,143.47 v2(105.83,142.25)
  L4_SIG w0.635: 104.62,171.75 104.62,143.47
  BOTTOM w0.2: R31.2 v2(105.83,142.25)
  BOTTOM w0.508: R37.1 v2(108.31,118.65)
  vias: v1(75.23,176.28) v1(75.23,175.01) v1(75.23,173.75) v1(78.68,176.31) v1(78.68,175.04) v1(78.68,173.77) v1(78.68,172.5) v1(81.5,163.2) v1(81.5,161.87) v1(81.5,160.53) v1(82.84,163.2) v1(82.84,161.87) v1(82.84,160.53) v1(84.17,163.2) v1(84.17,161.87) v1(84.17,160.53) v1(85.5,163.2) v1(85.5,161.87) v1(85.5,160.53) v1(86.25,176.28) v1(86.25,175.01) v1(86.25,173.75) v1(86.25,172.47) v1(87.45,163.2) v1(87.45,161.87) v1(87.45,160.53) v1(88.78,163.2) v1(88.78,161.87) v1(88.78,160.53) v1(89.71,176.31) v1(89.71,175.04) v1(89.71,173.77) v1(89.71,172.5) v1(90.12,163.2) v1(90.12,161.87) v1(90.12,160.53) v1(91.45,163.2) v1(91.45,161.87) v1(91.45,160.53) v1(97.33,176.31) v1(97.33,175.04) v1(97.33,173.77) v1(97.33,172.5) v1(100.78,176.34) v1(100.78,175.07) v1(100.78,173.8) v1(103.33,175.94) v1(103.33,173.4) v1(104.6,174.67) v1(105.87,175.94) v1(105.87,173.4) v1(108.37,176.28) v1(108.37,175.01) v1(108.37,173.75) v1(111.83,176.31) v1(111.83,175.04) v1(111.83,173.77) v1(111.83,172.5) v1(117.59,163.2) v1(117.59,161.87) v1(117.59,160.53) v1(118.92,163.2) v1(118.92,161.87) v1(118.92,160.53) v1(119.47,176.28) v1(119.47,175.01) v1(119.47,173.75) v1(119.47,172.47) v1(120.25,163.2) v1(120.25,161.87) v1(120.25,160.53) v1(121.59,163.2) v1(121.59,161.87) v1(121.59,160.53) v1(122.93,176.31) v1(122.93,175.04) v1(122.93,173.77) v1(122.93,172.5) v1(123.53,163.2) v1(123.53,161.87) v1(123.53,160.53) v1(124.87,163.2) v1(124.87,161.87) v1(124.87,160.53) v1(126.2,163.2) v1(126.2,161.87) v1(126.2,160.53) v1(127.53,163.2) v1(127.53,161.87) v1(127.53,160.53) v1(130.52,176.26) v1(130.52,174.99) v1(130.52,173.72) v1(130.52,172.45) v1(133.98,176.28) v1(133.98,175.01) v1(133.98,173.75) v1(133.98,172.47) v1(135.32,179.02) v1(135.32,177.75) v1(135.32,171.66) v1(135.32,170.39) v1(136.59,179.02) v1(136.59,177.75) v1(136.59,171.66) v1(136.59,170.39)
VLOW_P: length 189.5
  TOP w0.6: J2.1 161.1,109.31 C116.2 C39.2 156.62,108.18
  L2_PWR w0.5: 85.34,123.53 85.34,133.37 94.78,142.82 v2(101.39,142.82)
  L3_SIG w0.5: v2(106.16,54.21) 111.96,54.21 117.79,48.38 117.79,30.7 113.39,26.3 v1(91.67,26.3)
  L4_SIG w0.5: v2(117.73,120.36) 134.23,120.36 144.98,109.61 v1(144.98,107.29) ; v1(141.55,107.26) 134.42,114.39 98.97,114.39 97.9,115.47 v2(97.9,116.13)
  BOTTOM w0.2: R86.2 v2(106.16,54.21) ; R54.2 v2(77.21,123.18) ; R56.2 v2(131.84,123.18)
  BOTTOM w0.508: R36.2 v2(101.39,142.82) ; R92.1 v2(108.44,28.53) ; R40.2 v2(117.73,120.36) ; R75.2 v2(99.61,28.19) ; R80.2 v2(101.19,28.19) ; R6.1 v2(97.9,116.13)
  BOTTOM w1.016: C94.2 v1(91.67,26.3) ; C70.2 v1(88.12,26.3)
  vias: v1(45.96,106.89) v1(45.96,104.35) v1(45.95,96.73) v1(45.95,94.19) v1(47.23,105.62) v1(47.22,95.46) v1(48.5,106.89) v1(48.5,104.35) v1(48.49,96.73) v1(48.49,94.19) v1(49.77,105.62) v1(49.76,95.46) v1(51.04,106.89) v1(51.04,104.35) v1(51.04,101.81) v1(51.04,99.27) v1(51.03,96.73) v1(51.03,94.19) v1(52.3,95.46) v1(52.31,105.62) v1(52.31,103.08) v1(52.31,100.54) v1(52.31,98) v1(53.58,106.89) v1(53.58,104.35) v1(53.58,101.81) v1(53.58,99.27) v1(53.57,96.73) v1(53.57,94.19) v1(64.16,107.21) v1(64.16,105.94) v1(64.16,104.67) v1(64.16,103.4) v1(67.58,107.24) v1(67.58,105.97) v1(67.58,104.7) v1(67.58,103.43) v1(75.2,107.24) v1(75.2,105.97) v1(75.2,104.7) v1(75.2,103.43) v1(75.86,119.04) v1(77.2,119.04) v1(78.53,119.04) v1(78.63,107.26) v1(78.63,105.99) v1(78.63,104.72) v1(78.63,103.45) v1(82.01,82.95) v1(82.01,81.62) v1(82.01,80.29) v1(83.35,82.95) v1(83.35,81.62) v1(83.35,80.29) v1(84.68,82.95) v1(84.68,81.62) v1(84.68,80.29) v1(86.01,82.95) v1(86.01,81.62) v1(86.01,80.29) v1(86.33,107.21) v1(86.33,105.94) v1(86.33,104.67) v1(86.33,103.4) v1(87.96,82.95) v1(87.96,81.62) v1(87.96,80.29) v1(89.29,82.95) v1(89.29,81.62) v1(89.29,80.29) v1(89.76,107.24) v1(89.76,105.97) v1(89.76,104.7) v1(89.76,103.43) v1(90.63,82.95) v1(90.63,81.62) v1(90.63,80.29) v1(91.96,82.95) v1(91.96,81.62) v1(91.96,80.29) v1(97.38,107.21) v1(97.38,105.94) v1(97.38,104.67) v1(97.38,103.4) v1(100.81,107.24) v1(100.81,105.97) v1(100.81,104.7) v1(100.81,103.43) v1(108.4,107.21) v1(108.4,105.94) v1(108.4,104.67) v1(108.4,103.4) v1(111.83,107.24) v1(111.83,105.97) v1(111.83,104.7) v1(111.83,103.43) v1(117.23,82.95) v1(117.23,81.62) v1(117.23,80.29) v1(118.56,82.95) v1(118.56,81.62) v1(118.56,80.29) v1(119.48,107.24) v1(119.48,105.97) v1(119.48,104.7) v1(119.48,103.43) v1(119.9,82.95) v1(119.9,81.62) v1(119.9,80.29) v1(121.23,82.95) v1(121.23,81.62) v1(121.23,80.29) v1(122.91,107.26) v1(122.91,105.99) v1(122.91,104.72) v1(122.91,103.45) v1(123.18,82.95) v1(123.18,81.62) v1(123.18,80.29) v1(124.51,82.95) v1(124.51,81.62) v1(124.51,80.29) v1(125.85,82.95) v1(125.85,81.62) v1(125.85,80.29) v1(127.18,82.95) v1(127.18,81.62) v1(127.18,80.29) v1(130.49,119.04) v1(130.55,107.26) v1(130.55,105.99) v1(130.55,104.72) v1(130.55,103.45) v1(131.83,119.04) v1(133.16,119.04) v1(133.98,107.29) v1(133.98,106.02) v1(133.98,104.75) v1(133.98,103.48) v1(141.55,105.99) v1(141.55,104.72) v1(141.55,103.45) v1(144.98,106.02) v1(144.98,104.75) v1(144.98,103.48) v1(154.97,106.89) v1(154.97,104.35) v1(154.97,101.81) v1(154.97,99.27) v1(154.98,96.73) v1(154.98,94.19) v1(156.24,105.62) v1(156.24,103.08) v1(156.24,100.54) v1(156.24,98) v1(156.25,95.46) v1(157.51,106.89) v1(157.51,104.35) v1(157.51,101.81) v1(157.51,99.27) v1(157.52,96.73) v1(157.52,94.19) v1(158.78,105.62) v1(158.79,95.46) v1(160.05,106.89) v1(160.05,104.35) v1(160.06,96.73) v1(160.06,94.19) v1(161.32,105.62) v1(161.33,95.46) v1(162.59,106.89) v1(162.59,104.35) v1(162.6,96.73) v1(162.6,94.19)
VNEG: length 74.3
  TOP w0.6: v1(161.18,39.29) C96.1 C117.1 J3.1
  TOP w0.66: C63.2 v1(133.49,77.37) ; C67.1 v1(112.3,77.33) ; C65.1 v1(75.68,77.37) ; C60.2 v1(96.87,77.33)
  L3_SIG w0.6: v1(56.83,35.4) 55.8,35.4 54.62,36.58
  L3_SIG w0.635: v2(47.35,63.68) 47.35,43.85 54.62,36.58
  BOTTOM w0.2: U2.35 v2(106.81,45.12) ; U2.28 v2(103.31,45.12) ; U2.26 v2(102.31,45.12) ; v2(104.56,42.04) 104.31,41.79 v2(104.31,38.96) U2.7 104.31,35.2 C52.2
  BOTTOM w0.508: R81.2 v2(101.98,31.25) ; C47.2 v2(113.14,32.41) ; C45.2 v2(110.74,32.41) ; C48.2 v2(113.14,30.71) ; R73.2 v2(95.64,31.25) ; R79.2 v2(89.77,46.64) ; R67.2 v2(89.77,41.9) ; R76.2 v2(100.4,31.25) ; R77.2 v2(119.35,45.06) ; R94.2 v2(108.44,32.41) ; R71.1 v2(122.44,43.48) ; R69.2 v2(98.82,31.25) ; C49.1 v2(97.24,31.23) ; C56.2 v2(101.66,51.13) ; C52.2 v2(103.61,33.25) ; R97.2 v2(115.14,30.81) ; R63.1 v2(89.77,43.48) ; C53.1 v2(106.16,51.13) ; v2(110.74,30.71) C46.2 ; R74.2 v2(122.44,41.9) ; C50.1 v2(110.58,37.56)
  BOTTOM w0.581: Q15.2 v2(47.35,63.68)
  BOTTOM w1.016: 88.12,30.55 v1(88.12,31.95) ; 91.67,30.55 v1(91.67,31.95)
  vias: v1(56.5,77.87) v1(56.5,76.66) v1(56.83,39.05) v1(56.83,37.83) v1(56.83,36.62) v1(59.81,77.87) v1(59.81,76.66) v1(60.14,39.05) v1(60.14,37.83) v1(60.14,36.62) v1(60.14,35.4) v1(67.91,39.05) v1(67.91,37.83) v1(67.91,36.62) v1(67.91,35.4) v1(71.21,39.05) v1(71.21,37.83) v1(71.21,36.62) v1(71.21,35.4) v1(78.96,39.05) v1(78.96,37.83) v1(78.96,36.62) v1(78.96,35.4) v1(82.26,39.05) v1(82.26,37.83) v1(82.26,36.62) v1(82.26,35.4) v1(96.66,73.63) v1(96.66,71.59) v1(96.66,69.56) v1(96.66,67.53) v1(97.68,72.61) v1(97.68,70.58) v1(97.68,68.55) v1(97.68,66.51) v1(98.69,73.63) v1(98.69,71.59) v1(98.69,69.56) v1(98.69,67.53) v1(110.6,74.91) v1(110.6,72.87) v1(110.6,70.84) v1(110.6,68.81) v1(111.61,73.89) v1(111.61,71.86) v1(111.61,69.83) v1(111.61,67.79) v1(112.63,74.91) v1(112.63,72.87) v1(112.63,70.84) v1(112.63,68.81) v1(126.89,39.05) v1(126.89,37.83) v1(126.89,36.62) v1(126.89,35.4) v1(130.19,39.05) v1(130.19,37.83) v1(130.19,36.62) v1(130.19,35.4) v1(137.94,39.05) v1(137.94,37.83) v1(137.94,36.62) v1(137.94,35.4) v1(141.24,39.05) v1(141.24,37.83) v1(141.24,36.62) v1(141.24,35.4) v1(149.01,39.05) v1(149.01,37.83) v1(149.01,36.62) v1(149.01,35.4) v1(149.39,77.88) v1(149.39,76.66) v1(152.31,39.05) v1(152.31,37.83) v1(152.31,36.62) v1(152.31,35.4) v1(152.69,77.88) v1(152.69,76.66) v1(179.98,138.68) v1(179.98,62.48) v1(181.61,142.54) v1(181.61,134.82) v1(181.61,66.34) v1(181.61,58.62) v1(185.47,144.18) v1(185.47,133.19) v1(185.47,67.98) v1(185.47,56.99) v1(189.33,142.54) v1(189.33,134.82) v1(189.33,66.34) v1(189.33,58.62) v1(190.96,138.68) v1(190.96,62.48) v2(103.29,43.31) v2(103.29,42.04) v2(103.29,40.77) v2(103.44,52.42) v2(103.92,42.67) v2(103.92,41.4) v2(104.21,52.42) v2(104.56,43.31) v2(104.56,40.77) v2(105.19,42.67) v2(105.19,41.4) v2(105.83,43.31) v2(105.83,42.04) v2(105.83,40.77)
VPOS:
  vias: v1(165.2,188.79) v1(165.2,186.25) v1(165.18,178.63) v1(165.18,176.09) v1(165.15,106.89) v1(165.15,104.35) v1(165.13,96.73) v1(165.13,94.19) v1(166.47,187.52) v1(166.45,177.36) v1(166.42,105.62) v1(166.4,95.46) v1(167.69,106.89) v1(167.69,104.35) v1(167.67,96.73) v1(167.67,94.19) v1(167.74,188.79) v1(167.74,186.25) v1(167.72,178.63) v1(167.72,176.09) v1(168.99,177.36) v1(168.96,105.62) v1(168.94,95.46) v1(169.01,187.52) v1(170.28,188.79) v1(170.28,186.25) v1(170.28,183.71) v1(170.28,181.17) v1(170.26,178.63) v1(170.26,176.09) v1(170.23,106.89) v1(170.23,104.35) v1(170.23,101.81) v1(170.23,99.27) v1(170.21,96.73) v1(170.21,94.19) v1(171.5,105.62) v1(171.5,103.08) v1(171.5,100.54) v1(171.5,98) v1(171.48,95.46) v1(171.55,187.52) v1(171.55,184.98) v1(171.55,182.44) v1(171.55,179.9) v1(171.53,177.36) v1(172.77,106.89) v1(172.77,104.35) v1(172.77,101.81) v1(172.77,99.27) v1(172.75,96.73) v1(172.75,94.19) v1(172.82,188.79) v1(172.82,186.25) v1(172.82,183.71) v1(172.82,181.17) v1(172.8,178.63) v1(172.8,176.09) v1(180,113.3) v1(180.02,87.85) v1(181.63,117.16) v1(181.63,109.44) v1(181.65,91.71) v1(181.65,83.99) v1(185.49,118.79) v1(185.49,107.81) v1(185.51,93.35) v1(185.51,82.36) v1(189.35,117.16) v1(189.35,109.44) v1(189.37,91.71) v1(189.37,83.99) v1(190.98,113.3) v1(191,87.85)

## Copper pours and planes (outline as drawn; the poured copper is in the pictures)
GND_SIGNAL on TOP: 107.88,99.89 107.88,94.79 112.35,94.79 112.35,99.89
GND_SIGNAL on TOP: 141.07,99.89 141.07,94.79 145.54,94.79 145.54,99.89
GND_SIGNAL on TOP: 85.76,99.89 85.76,94.79 90.23,94.79 90.23,99.89
GND_SIGNAL on TOP: 85.76,184.95 85.76,179.85 90.23,179.85 90.23,184.95
GND_SIGNAL on TOP: 74.71,184.95 74.71,179.85 79.18,179.85 79.18,184.95
GND_SIGNAL on TOP: 96.8,184.95 96.8,179.85 101.27,179.85 101.27,184.95
GND_SIGNAL on TOP: 74.69,99.89 74.69,94.79 79.16,94.79 79.16,99.89
GND_SIGNAL on TOP: 107.83,184.95 107.83,179.85 112.3,179.85 112.3,184.95
GND_SIGNAL on TOP: 118.93,184.95 118.93,179.85 123.4,179.85 123.4,184.95
GND_SIGNAL on TOP: 130,184.95 130,179.85 134.47,179.85 134.47,184.95
GND_SIGNAL on TOP: 96.82,99.89 96.82,94.79 101.29,94.79 101.29,99.89
GND_SIGNAL on TOP: 118.94,99.89 118.94,94.79 123.41,94.79 123.41,99.89
GND_SIGNAL on TOP: 130,99.89 130,94.79 134.47,94.79 134.47,99.89
GND_SIGNAL on TOP: 63.63,99.89 63.63,94.79 68.1,94.79 68.1,99.89
GND_SIGNAL on TOP: 1.27,1.27 1.27,199.9 207.9,199.9 207.9,1.27 ; 5 cut-outs
GND_SIGNAL on TOP, BOTTOM, L2_PWR, L3_SIG, L4_SIG, L5_GND: 179.47,189.48 191.47,189.48
GND_SIGNAL on TOP, BOTTOM, L2_PWR, L3_SIG, L4_SIG, L5_GND: 179.51,11.67 191.51,11.67
GND_SIGNAL on TOP, L2_PWR, L3_SIG, L4_SIG, L5_GND: 179.47,164.08 191.47,164.08
GND_SIGNAL on TOP, L2_PWR, L3_SIG, L4_SIG, L5_GND: 17.71,75.15 29.71,75.15
GND_SIGNAL on TOP, L2_PWR, L3_SIG, L4_SIG, L5_GND: 179.47,37.14 191.47,37.14
GND_SIGNAL on TOP, L2_PWR, L3_SIG, L4_SIG, L5_GND: 17.71,49.78 29.71,49.78
GND_SIGNAL on BOTTOM: 1.27,1.27 1.27,199.9 207.9,199.9 207.9,1.27 ; 51 cut-outs
GND_SIGNAL on L2_PWR, L5_GND: 1.27,1.27 207.9,1.27 207.9,199.9 1.27,199.9
GND_SIGNAL on L3_SIG: 1.27,1.27 1.27,199.9 207.9,199.9 207.9,1.27 ; 10 cut-outs
GND_SIGNAL on L4_SIG: 1.27,1.27 1.27,199.9 207.9,199.9 207.9,1.27 ; 12 cut-outs
V5_P on BOTTOM: 43.82,55.98 43.82,54.05 42.5,54.05 42.5,55.98
VIN on TOP: 1.27,82.19 1.27,164.43 44.36,164.43 44.36,82.19
VIN on BOTTOM: 44.36,164.42 44.36,82.19 1.27,82.19 1.27,164.42
VIN on L2_PWR: 17.65,145.73 29.65,145.73
VIN on L2_PWR, L5_GND: 17.65,120.33 29.65,120.33
VIN on L3_SIG: 17.68,120.32 29.68,120.32
VIN on L3_SIG: 17.65,145.75 29.65,145.75
VIN on L4_SIG: 17.7,145.73 29.7,145.73
VIN on L4_SIG: 17.65,120.35 29.65,120.35
VIN on L5_GND: 17.67,145.73 29.67,145.73
(no net) on BOTTOM: 99.19,133.98 98.1,135.07 95.45,135.07 95.45,132.8 98.3,132.8 98.3,132.38 99.19,132.38
(no net) on BOTTOM: 104.64,50.68 104.64,52.68 103.01,52.68 103.01,50.68
(no net) on BOTTOM: 102.78,138.01 102.78,135.53 103.53,134.78 103.53,133.51 103.83,133.51 103.83,134.78 104.57,135.51 104.57,138.01
(no net) on BOTTOM: 109.67,133.98 110.76,135.07 113.42,135.07 113.42,132.8 110.56,132.8 110.56,132.38 109.67,132.38
(no net) on BOTTOM: 97.58,136.07 97.58,137.67 96.18,137.67 96.18,136.07
(no net) on BOTTOM: 97.7,48.13 97.7,49.73 96.31,49.73 96.31,48.13
(no net) on BOTTOM: 99.32,46.04 98.24,47.13 95.58,47.13 95.58,44.86 98.43,44.86 98.43,44.44 99.32,44.44
(no net) on BOTTOM: 112.69,136.07 112.69,137.67 111.29,137.67 111.29,136.07
(no net) on BOTTOM: 109.79,46.04 110.88,47.13 113.54,47.13 113.54,44.92 110.69,44.92 110.69,44.44 109.79,44.44
(no net) on BOTTOM: 112.81,48.13 112.81,49.73 111.42,49.73 111.42,48.13
DRVCC_N on BOTTOM (solid shape): 97.7,48.13 96.31,48.13 96.31,49.73 97.7,49.73
DRVCC_N on BOTTOM (solid shape): 112.81,48.13 111.42,48.13 111.42,49.73 112.81,49.73
DRVCC_N on BOTTOM: 102.99,50.07 102.99,47.49 103.66,46.82 103.66,45.57 103.96,45.57 103.96,46.82 104.64,47.49 104.64,50.07
DRVCC_P on BOTTOM (solid shape): 97.58,136.07 96.18,136.07 96.18,137.67 97.58,137.67
DRVCC_P on BOTTOM (solid shape): 112.69,136.07 111.29,136.07 111.29,137.67 112.69,137.67
DRVCC_P on BOTTOM (solid shape): 104.57,135.51 103.83,134.78 103.83,134.68 103.83,133.51 103.54,133.51 103.54,134.68 103.53,134.78 102.78,135.53 102.78,138.01 104.57,138.01
RUN_P on BOTTOM: 35.57,126.7 35.57,125.29 38.7,125.29 38.7,126.7
UNNAMED_7_CAP_I87_N1 on TOP: 77.26,159.08 77.26,143.21 93.46,143.21 93.46,159.08
UNNAMED_7_CAP_I87_N1 on BOTTOM: 77.26,159.07 77.26,143.2 93.46,143.2 93.46,159.07
UNNAMED_7_CAP_I87_N2 on BOTTOM (solid shape): 99.19,133.98 99.19,132.38 98.3,132.38 98.3,132.8 95.45,132.8 95.45,135.07 98.1,135.07
UNNAMED_7_CAP_I93_N1 on TOP: 131.79,159.08 131.79,143.21 115.56,143.21 115.56,159.08
UNNAMED_7_CAP_I93_N1 on BOTTOM: 115.56,159.07 115.56,143.2 131.76,143.2 131.76,159.07
UNNAMED_7_CAP_I93_N2 on BOTTOM (solid shape): 113.42,132.8 110.56,132.8 110.56,132.38 109.67,132.38 109.67,133.98 110.76,135.07 113.42,135.07
UNNAMED_7_ICLTC3871_I31_BG1 on BOTTOM: 107.03,133.51 107.03,134.68 107.28,134.68 109.23,136.64 109.23,137.3 110.56,137.3 110.56,136.46 110.38,136.46 107.43,133.51
UNNAMED_7_ICLTC3871_I31_BG2 on BOTTOM: 98.31,137.3 98.31,136.46 98.49,136.46 101.44,133.51 101.83,133.51 101.83,134.68 101.56,134.68 99.61,136.64 99.61,137.3
UNNAMED_7_IND_I144_N2 on TOP: 122.1,124.29 122.1,142.57 139.63,142.57 139.63,124.29
UNNAMED_7_IND_I144_N2 on BOTTOM: 122.09,142.56 139.64,142.56 139.64,124.3 132.72,124.3 132.72,126.15 126.82,126.15 126.82,124.3 122.09,124.3
UNNAMED_7_IND_I265_N1 on TOP: 87.09,124.29 87.09,142.57 69.56,142.57 69.56,124.29
UNNAMED_7_IND_I265_N1 on BOTTOM: 69.56,142.56 87.09,142.56 87.09,124.3 82.22,124.3 82.22,126 76.32,126 76.32,124.3 69.56,124.3
UNNAMED_9_CAP_I91_N1 on TOP: 76.92,78.83 76.92,62.96 93.97,62.96 93.97,78.83
UNNAMED_9_CAP_I91_N1 on BOTTOM: 76.93,78.83 76.93,62.96 93.97,62.96 93.97,78.83
UNNAMED_9_CAP_I91_N2 on BOTTOM (solid shape): 99.32,46.04 99.32,44.44 98.43,44.44 98.43,44.86 95.58,44.86 95.58,47.13 98.24,47.13
UNNAMED_9_CAP_I93_N1 on TOP: 132.24,78.83 132.24,62.96 115.22,62.96 115.22,78.83
UNNAMED_9_CAP_I93_N1 on BOTTOM: 115.13,78.83 115.13,62.96 132.17,62.96 132.17,78.83
UNNAMED_9_CAP_I93_N2 on BOTTOM (solid shape): 113.54,44.92 110.69,44.92 110.69,44.44 109.79,44.44 109.79,46.04 110.88,47.13 113.54,47.13
UNNAMED_9_ICLTC3871_I21_BG1 on BOTTOM: 107.16,45.59 107.16,46.75 107.41,46.75 109.36,48.71 109.36,49.37 110.68,49.37 110.68,48.52 110.5,48.52 107.56,45.59
UNNAMED_9_ICLTC3871_I21_BG2 on BOTTOM: 98.44,49.36 98.44,48.5 98.65,48.5 101.57,45.57 101.96,45.57 101.96,46.74 101.72,46.74 99.76,48.7 99.76,49.36
UNNAMED_9_IND_I114_N1 on TOP: 93.97,62.33 93.97,49.05 76.92,49.05 76.92,62.33
UNNAMED_9_IND_I114_N1 on BOTTOM: 76.92,62.33 93.97,62.33 93.97,58.39 91.7,58.39 91.7,52.48 93.97,52.48 93.97,49.05 76.92,49.05
UNNAMED_9_IND_I133_N2 on TOP: 115.22,62.33 115.22,49.03 132.24,49.03 132.24,62.33
UNNAMED_9_IND_I133_N2 on BOTTOM: 115.22,62.33 132.24,62.33 132.24,49.03 115.22,49.03 115.22,52.48 117.01,52.48 117.01,58.39 115.22,58.39
VHIGH on TOP: 1.27,199.9 1.27,165.04 163.54,165.04 163.54,199.9
VHIGH on BOTTOM: 1.27,165.06 163.54,165.06 163.54,199.9 1.27,199.9
VHIGH on L2_PWR: 1.27,165.06 163.55,165.06 163.55,199.9 1.27,199.9
VHIGH_P on TOP: 72.91,159.73 72.91,181.98 140.09,181.98 140.09,165.06 136.29,165.06 136.29,159.73 115.75,159.73 115.75,161.63 93.46,161.63 93.46,159.73
VHIGH_P on BOTTOM: 136.29,159.73 115.76,159.73 115.76,161.64 93.46,161.64 93.46,159.73 72.89,159.73 72.89,182.01 140.09,182.01 140.09,165.06 136.29,165.06
VHIGH_P on L2_PWR: 72.91,181.98 72.91,159.73 93.46,159.73 93.46,161.63 115.75,161.63 115.75,159.73 136.29,159.73 136.29,165.04 140.08,165.04 140.09,165.06 140.09,181.98
VLOW_P on TOP: 122.08,123.65 139.63,123.65 139.63,108.26 163.54,108.26 163.54,79.49 105.21,79.48 104.58,79.48 103.95,79.48 45,79.49 45,108.26 69.56,108.26 69.56,123.65 87.09,123.65 87.09,113 122.08,113
VLOW_P on BOTTOM: 122.06,113 122.06,123.69 126.82,123.68 126.82,121.95 132.72,121.95 132.72,123.67 139.64,123.66 139.64,108.27 163.54,108.26 163.54,79.47 45,79.47 45,108.27 69.56,108.27 69.56,123.66 76.32,123.66 76.32,121.95 82.22,121.95 82.22,123.66 87.08,123.66 87.07,113.01 87.09,112.99
VLOW_P on L2_PWR: 163.59,123.64 163.59,79.48 55.31,79.49 55.31,29.1 109.16,29.1 109.16,25.62 51.88,25.62 51.88,79.52 45,79.52 45,123.64 87.09,123.64 87.09,113 122.09,113 122.09,123.64
VNEG on BOTTOM (solid shape): 104.64,50.7 103.01,50.7 103.01,52.68 104.64,52.68
VNEG on TOP: 55.95,81.06 55.95,75.97 60.42,75.97 60.42,81.06
VNEG on TOP: 148.84,81.07 148.84,75.97 153.31,75.97 153.31,81.07
VNEG on TOP: 114.57,66.75 114.57,75.89 108.57,75.89 108.57,66.75
VNEG on TOP: 179.47,149.29 207.9,149.29 207.9,1.27 53.3,1.27 53.3,39.77 53.36,39.82 82.87,39.79 82.87,24.55 126.33,24.55 126.33,39.8 157.84,39.8 157.85,39.79 158.59,39.79 158.6,39.8 164.17,39.8 164.17,75.2 192.14,75.2 192.14,124.73 179.47,124.73
VNEG on TOP: 78.41,39.81 78.41,34.71 82.88,34.71 82.88,39.81
VNEG on TOP: 100.63,65.47 100.63,74.61 94.63,74.61 94.63,65.47
VNEG on TOP: 71.9,78.84 71.9,76.87 76.29,76.87 76.29,78.84
VNEG on TOP: 56.28,39.81 56.28,34.71 60.75,34.71 60.75,39.81
VNEG on TOP: 137.39,39.81 137.39,34.71 141.86,34.71 141.86,39.81
VNEG on TOP: 67.36,39.81 67.36,34.71 71.83,34.71 71.83,39.81
VNEG on TOP: 126.34,39.81 126.34,34.71 130.81,34.71 130.81,39.81
VNEG on TOP: 148.46,39.81 148.46,34.71 152.93,34.71 152.93,39.81
VNEG on TOP: 132.88,78.84 132.88,76.87 137.3,76.87 137.3,78.84
VNEG on TOP, L2_PWR, L3_SIG, L4_SIG, L5_GND: 179.47,138.68 191.47,138.68
VNEG on TOP, L2_PWR, L3_SIG, L4_SIG, L5_GND: 179.47,62.48 191.47,62.48
VNEG on BOTTOM: 179.47,149.29 207.89,149.29 207.89,1.27 53.3,1.27 53.3,39.79 82.87,39.79 82.87,24.58 126.34,24.58 126.34,39.81 164.17,39.81 164.17,75.2 192.14,75.2 192.14,124.73 179.47,124.73
VNEG on L2_PWR: 56.08,29.74 55.99,78.86 163.59,78.86 163.59,29.74
VNEG on L5_GND: 53.33,78.86 53.33,29.74 163.59,29.74 163.59,78.86
VPOS on TOP: 191.51,75.84 164.17,75.84 164.17,124.1 191.51,124.1
VPOS on TOP: 207.9,149.93 178.83,149.93 178.83,118.43 164.17,118.43 164.17,199.9 207.9,199.9
VPOS on TOP, L2_PWR, L3_SIG, L4_SIG, L5_GND: 179.49,113.3 191.49,113.3
VPOS on TOP, L2_PWR, L3_SIG, L4_SIG, L5_GND: 179.51,87.85 191.51,87.85
VPOS on BOTTOM: 164.17,199.9 207.9,199.9 207.9,149.92 178.83,149.92 178.83,124.1 191.51,124.1 191.51,75.83 164.17,75.83

Small or netless copper shapes (teardrops, artwork), in the pictures only: 10 on BOTTOM

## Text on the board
Ref Des/Silkscreen Bottom: 08-068614 REV B Z | SECONDARY SIDE | C | A
User.Comments: 6.    SEE "DETAIL A" TO INSTALL  KFH-032-10ET: | > SPECIFICALLY FOR P1, P2, P3, P4, P6, P7, P8, P9, P12, P13, | P14, P15 ONLY. | 5.    INSTALL SCREW (M025339) ON PRIMARY SIDE | AND STANDOFF (M025474) ON SECONDARY SIDE | SEE NOTE #5 | SEE NOTE #8 | SEE NOTE #6 | (4 PLACES) | 10.    SHORT THE DRAIN-SOURCE OF Q10 AND Q18, WITH 0805 0-OHM RESISTOR. | 11.    REPLACE D2 WITH 0805 0-OHM RESISTOR. | 12.    SHORT THE DRAIN-SOURCE OF Q10 WTIH 0805 0-OHM RESISTOR | 13.    REPLACE D4 WITH 0805 0-OHM RESISTOR. | MAKE SURE NOT TO SHORT THE "GATE" OF Q10 WITH OTHER FET TERMINALS. | 14.    SHORT THE DRAIN-SOURCE OF Q18 WTIH 0805 0-OHM RESISTOR | (12 PLACES) | MAKE SURE NOT TO SHORT THE "GATE" OF Q10 AND Q18, WITH OTHER FET TERMINALS. | MAKE SURE NOT TO SHORT THE "GATE" OF Q18 WITH OTHER FET TERMINALS. | FOR 17.5V (BOM 05-068614-01) VARIANT: | FOR 9V (BOM 05-068614-03) VARIANT: | 9.    REPLACE D2 AND D4 WITH 0805 0-OHM RESISTOR. | FOR 32.5V AND 30V (BOM 05-068614-02/ 05-068614-06) VARIANTS: | 7.    INSTALL JUMPER SHUNT (M022926) ON POSITIONS 1 AND 2 OF P5. | 8.    ATTACH STICKER LABEL PER BOM VARIANT DECLARATION: | MFG_PN: 4705 | * P17V5N17V5 FOR 05-068614-01 | *  P32V5N3V  FOR 05-068614-02 | *  P9VN5V5   FOR 05-068614-03 | *  P30VN5V   FOR 05-068614-06 | * P23V5N15V  FOR 05-068614-04 | NOT TO SCALE | DETAIL A | MFG_PN: KFH-032-10ET | WASHER, LOCK STEEL 3/64 | MFG_PN: 1477 | MFG_PN: 4703
Ref Des/Silkscreen Top: ON | OFF | VIN | GND | A | C | 08-068614 REV B Z | PRIMARY SIDE | VNEG | VPOS
PAGE_OUTLINE: B | CHANGES AS PER ECR-106439 | CHANGES AS PER ECR-122459 | 22APR22 | 04SEP24 | R. AURORA | J. SANCHEZ | CUSTOMER EVALUATION Z
BODY_CENTER: NOTE: ALL IMPEDANCE TOLERANCE +/-10% | LAYER | L1 | SE = SINGLE ENDED, DP = DIFFERENTIAL PAIR | 50 OHMS SE | IMPEDANCE | REFERENCE | L2 | LINE WIDTH | 0.100MM | SPACE | N/A | IMPEDANCE TABLE
DIMENSION: - | " " | (REF) | DIA MAX
DISPLAY_TOP: 15.    BOARDS TO BE SHIPPED IN ARRAYS.
User.11: C | A
User.12: A | C
User.27: L2 PWR | 08-      -07
User.28: L3 SIG | 08-      -08
User.29: L4 SIG | 08-      -09
User.30: L5 GND | 08-      -10
User.45: FIGURE | SIZE | 0.254 | 0.508 | 0.762 | 0.889 | 4.851 | 3.175 | DRILL CHART: TOP to BOTTOM | FINISHED HOLES IN MILLIMETERS | PLATED | NON-PLATED | QTY | 222 | 1258 | 12 | 3 | 4 | TOLERANCE/NOTES
